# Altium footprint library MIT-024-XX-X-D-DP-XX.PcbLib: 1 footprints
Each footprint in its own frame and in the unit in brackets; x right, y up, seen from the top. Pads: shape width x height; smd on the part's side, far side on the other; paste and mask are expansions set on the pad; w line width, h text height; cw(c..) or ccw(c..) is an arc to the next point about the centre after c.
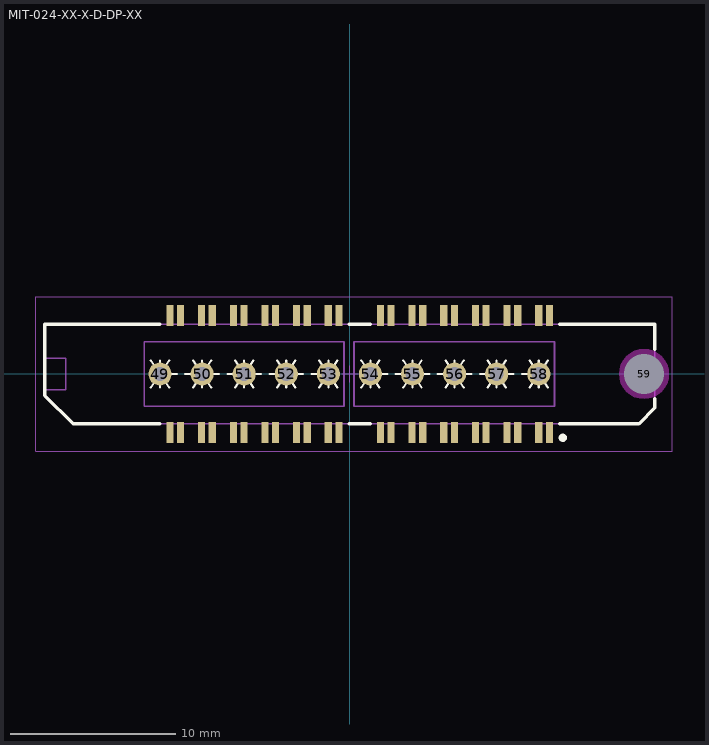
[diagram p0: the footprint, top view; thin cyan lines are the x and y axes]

## MIT-024-XX-X-D-DP-XX [mm] "0.635mm pitch, 48 pin, mixed technology high speed terminal; differential"
height 4.27
pads (59):
  rect 0.43x1.25 smd mask+0: 1(12.04,-3.531) 2(12.04,3.529) 3(11.4,-3.531) 4(11.4,3.529) 5(10.13,-3.531) 6(10.13,3.529) 7(9.49,-3.531) 8(9.49,3.529) 9(8.22,-3.531) 10(8.22,3.529) 11(7.58,-3.531) 12(7.58,3.529) 13(6.31,-3.531) 14(6.31,3.529) 15(5.67,-3.531) 16(5.67,3.529) 17(4.4,-3.531) 18(4.4,3.529) 19(3.76,-3.531) 20(3.76,3.529) 21(2.49,-3.531) 22(2.49,3.529) 23(1.85,-3.531) 24(1.85,3.529) 25(-0.66,-3.531) 26(-0.66,3.529) 27(-1.3,-3.531) 28(-1.3,3.529) 29(-2.57,-3.531) 30(-2.57,3.529) 31(-3.21,-3.531) 32(-3.21,3.529) 33(-4.48,-3.531) 34(-4.48,3.529) 35(-5.12,-3.531) 36(-5.12,3.529) 37(-6.39,-3.531) 38(-6.39,3.529) 39(-7.03,-3.531) 40(-7.03,3.529) 41(-8.3,-3.531) 42(-8.3,3.529) 43(-8.94,-3.531) 44(-8.94,3.529) 45(-10.21,-3.531) 46(-10.21,3.529) 47(-10.85,-3.531) 48(-10.85,3.529)
  round 1.4 hole 0.85 mask+0: 49(-11.455,-0.001) 50(-8.915,-0.001) 51(-6.375,-0.001) 52(-3.835,-0.001) 53(-1.295,-0.001) 54(1.24,-0.001) 55(3.78,-0.001) 56(6.32,-0.001) 57(8.86,-0.001) 58(11.4,-0.001)
  round 1 hole 2.4 unplated mask+0: 59(17.75,-0.001)
Top Overlay:
  circle w0.25: c12.85,-3.85 r0.125
  lines w0.127: -12.011,-0.826 -10.899,0.824 ; -12.011,0.824 -10.899,-0.826 ; -11.455,-0.826 -11.455,0.824 ; -11.455,-0.001 -10.44,-0.001 ; -9.93,-0.001 -7.9,-0.001 ; -9.471,-0.826 -8.359,0.824 ; -9.471,0.824 -8.359,-0.826 ; -8.915,-0.826 -8.915,0.824 ; -7.39,-0.001 -5.36,-0.001 ; -6.931,-0.826 -5.819,0.824 ; -6.931,0.824 -5.819,-0.826 ; -6.375,-0.826 -6.375,0.824 ; -4.85,-0.001 -2.82,-0.001 ; -4.391,-0.826 -3.279,0.824 ; -4.391,0.824 -3.279,-0.826 ; -3.835,-0.826 -3.835,0.824 ; 0.684,-0.826 1.796,0.824 ; 0.684,0.824 1.796,-0.826 ; 1.24,-0.826 1.24,0.824 ; 1.24,-0.001 2.255,-0.001 ; 2.765,-0.001 4.795,-0.001 ; 3.224,-0.826 4.336,0.824 ; 3.224,0.824 4.336,-0.826 ; 3.78,-0.826 3.78,0.824 ; 5.305,-0.001 7.335,-0.001 ; 5.764,-0.826 6.876,0.824 ; 5.764,0.824 6.876,-0.826 ; 6.32,-0.826 6.32,0.824 ; 7.845,-0.001 9.875,-0.001 ; 8.304,-0.826 9.416,0.824 ; 8.304,0.824 9.416,-0.826 ; 8.86,-0.826 8.86,0.824
  lines w0.13: -2.31,-0.001 -1.295,-0.001 ; -1.851,-0.826 -0.739,0.824 ; -1.851,0.824 -0.739,-0.826 ; -1.295,-0.826 -1.295,-0.001 ; -1.295,0.824 -1.295,-0.001 ; 10.385,-0.001 11.4,-0.001 ; 10.844,-0.826 11.956,0.824 ; 10.844,0.824 11.956,-0.826 ; 11.4,-0.826 11.4,-0.001 ; 11.4,0.824 11.4,-0.001
  lines w0.2: -11.45,-3 -16.7,-3 -18.4,-1.3 -18.4,3 -11.45,3 ; -0.05,-3 1.25,-3 ; -0.05,3 1.25,3 ; 12.65,-3 17.45,-3 18.4,-2.05 18.4,-1.5 ; 12.65,3 18.4,3 18.4,1.5
Keep-Out Layer:
  pour cut-out: 19.257,0 19.228,0.294 19.143,0.577 19.003,0.837 18.816,1.066 18.587,1.253 18.327,1.393 18.044,1.478 17.75,1.507 17.456,1.478 17.173,1.393 16.913,1.253 16.684,1.066 16.497,0.837 16.357,0.577 16.272,0.294 16.243,0 16.272,-0.294 16.357,-0.577 16.497,-0.837 16.684,-1.066 16.913,-1.253 17.173,-1.393 17.456,-1.478 17.75,-1.507 18.044,-1.478 18.327,-1.393 18.587,-1.253 18.816,-1.066 19.003,-0.837 19.143,-0.577 19.228,-0.294
Mechanical 12:
  lines w0.001: -18.4,-1.265 -16.716,-3 17.464,-3 18.4,-2.049 18.4,-0.95 17.15,-0.95 17.15,0.95 18.4,0.95 18.4,3 -18.4,3 -18.4,0.95 -17.15,0.95 -17.15,-0.95 -18.4,-0.95 -18.4,-1.265
Mechanical 13:
  lines w0.06: -18.948,-4.674 19.45,-4.674 19.45,4.672 -18.948,4.672 -18.948,-4.674
  lines w0.1: -18.4,-1.265 -16.716,-3 17.464,-3 18.4,-2.049 18.4,-0.95 17.15,-0.95 17.15,0.95 18.4,0.95 18.4,3 -18.4,3 -18.4,0.95 -17.15,0.95 -17.15,-0.95 -18.4,-0.95 -18.4,-1.265 ; -12.4,-1.95 -0.35,-1.95 -0.35,1.95 -12.4,1.95 -12.4,-1.95 ; 0.25,-1.95 12.35,-1.95 12.35,1.95 0.25,1.95 0.25,-1.95
  text ".Designator" at 0.254,0.254 h1.52
Mechanical 15:
  lines w0.05: -0.5,0 0.5,0 ; 0,-0.5 0,0.5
